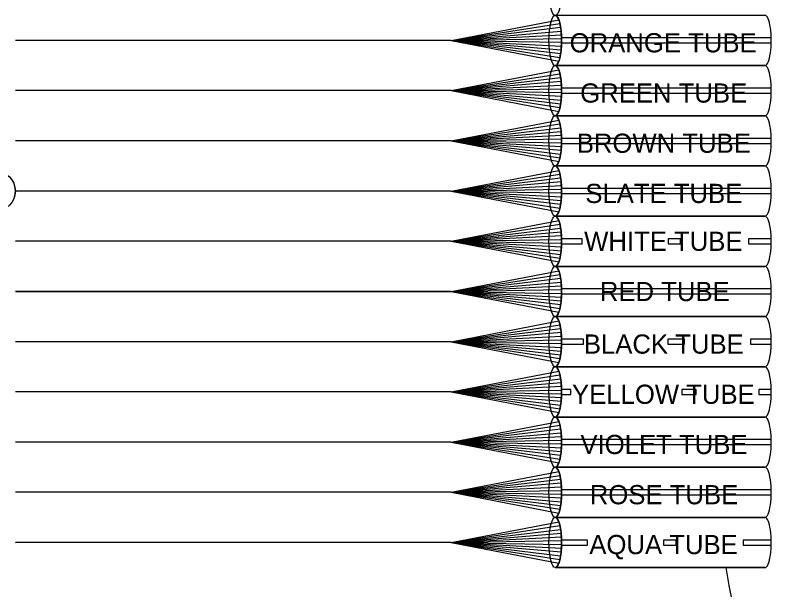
# Model space of a CAD drawing. Extents: x 1805893 to 1833564, y 708898 to 716199.
# Drawn here: x 1831739.1 to 1831830.8, y 715850.1 to 715918.7 of the extents above; entities that cross this region are included whole.
import ezdxf

# ---------------------------------------------------------------- set-up
doc = ezdxf.new("R2010")
doc.units = 0
doc.layers.add('SH_Data', color=7, linetype='Continuous')

msp = doc.modelspace()

# ---------------------------------------------------------------- linework, layer by layer
at = {"layer": 'SH_Data'}
for p, q in [((1831828.682, 715918.733), (1831803.631, 715918.733)), ((1831791.211, 715915.733), (1831804.055, 715918.208)), ((1831791.211, 715915.733), (1831804.185, 715917.758)), ((1831791.211, 715915.733), (1831804.27, 715917.308)), ((1831791.211, 715915.733), (1831804.327, 715916.858)), ((1831791.211, 715915.733), (1831739.139, 715915.733)), ((1831791.211, 715915.733), (1831739.139, 715915.733)), ((1831791.211, 715915.733), (1831804.362, 715916.408)), ((1831791.211, 715915.733), (1831804.379, 715915.958)), ((1831791.211, 715915.733), (1831804.327, 715914.608)), ((1831791.211, 715915.733), (1831804.27, 715914.158)), ((1831791.211, 715915.733), (1831804.185, 715913.708)), ((1831791.211, 715915.733), (1831804.055, 715913.258)), ((1831791.211, 715915.733), (1831804.362, 715915.058)), ((1831791.211, 715915.733), (1831804.379, 715915.508)), ((1831791.211, 715909.733), (1831804.055, 715912.208)), ((1831828.682, 715912.733), (1831803.631, 715912.733)), ((1831803.631, 715912.733), (1831828.682, 715912.733)), ((1831791.211, 715909.733), (1831804.185, 715911.758)), ((1831791.211, 715909.733), (1831804.27, 715911.308)), ((1831791.211, 715909.733), (1831804.327, 715910.858)), ((1831791.211, 715909.733), (1831804.362, 715910.408)), ((1831791.211, 715909.733), (1831739.139, 715909.733)), ((1831791.211, 715909.733), (1831739.139, 715909.733)), ((1831791.211, 715909.733), (1831804.379, 715909.958)), ((1831791.211, 715909.733), (1831804.327, 715908.608)), ((1831791.211, 715909.733), (1831804.27, 715908.158)), ((1831791.211, 715909.733), (1831804.185, 715907.708)), ((1831791.211, 715909.733), (1831804.055, 715907.258)), ((1831791.211, 715909.733), (1831804.362, 715909.058)), ((1831791.211, 715909.733), (1831804.379, 715909.508)), ((1831803.631, 715906.733), (1831828.682, 715906.733)), ((1831828.682, 715906.733), (1831803.631, 715906.733)), ((1831791.211, 715903.733), (1831804.055, 715906.208)), ((1831791.211, 715903.733), (1831804.185, 715905.758)), ((1831791.211, 715903.733), (1831804.27, 715905.308)), ((1831791.211, 715903.733), (1831804.327, 715904.858)), ((1831791.211, 715903.733), (1831739.139, 715903.733)), ((1831791.211, 715903.733), (1831739.139, 715903.733)), ((1831791.211, 715903.733), (1831804.362, 715904.408)), ((1831791.211, 715903.733), (1831804.379, 715903.958)), ((1831791.211, 715903.733), (1831804.327, 715902.608)), ((1831791.211, 715903.733), (1831804.27, 715902.158)), ((1831791.211, 715903.733), (1831804.185, 715901.708)), ((1831791.211, 715903.733), (1831804.055, 715901.258)), ((1831791.211, 715903.733), (1831804.362, 715903.058)), ((1831791.211, 715903.733), (1831804.379, 715903.508)), ((1831791.211, 715897.733), (1831804.055, 715900.208)), ((1831803.631, 715900.733), (1831828.682, 715900.733)), ((1831828.682, 715900.733), (1831803.631, 715900.733)), ((1831791.211, 715897.733), (1831804.185, 715899.758)), ((1831791.211, 715897.733), (1831804.27, 715899.308)), ((1831791.211, 715897.733), (1831804.327, 715898.858)), ((1831791.211, 715897.733), (1831804.362, 715898.408)), ((1831791.211, 715897.733), (1831739.139, 715897.733)), ((1831791.211, 715897.733), (1831739.139, 715897.733)), ((1831791.211, 715897.733), (1831804.379, 715897.958)), ((1831791.211, 715897.733), (1831804.327, 715896.608)), ((1831791.211, 715897.733), (1831804.27, 715896.158)), ((1831791.211, 715897.733), (1831804.185, 715895.708)), ((1831791.211, 715897.733), (1831804.055, 715895.258)), ((1831791.211, 715897.733), (1831804.362, 715897.058)), ((1831791.211, 715897.733), (1831804.379, 715897.508)), ((1831803.631, 715894.733), (1831828.682, 715894.733)), ((1831828.682, 715894.733), (1831803.631, 715894.733)), ((1831791.211, 715891.733), (1831804.055, 715894.208)), ((1831791.211, 715891.733), (1831804.185, 715893.758)), ((1831791.211, 715891.733), (1831804.27, 715893.308)), ((1831791.211, 715891.733), (1831804.327, 715892.858)), ((1831791.211, 715891.733), (1831739.139, 715891.711)), ((1831791.211, 715891.733), (1831739.139, 715891.733)), ((1831791.211, 715891.733), (1831804.362, 715892.408)), ((1831791.211, 715891.733), (1831804.379, 715891.958)), ((1831791.211, 715891.733), (1831804.327, 715890.608)), ((1831791.211, 715891.733), (1831804.27, 715890.158)), ((1831791.211, 715891.733), (1831804.185, 715889.708)), ((1831791.211, 715891.733), (1831804.055, 715889.258)), ((1831791.211, 715891.733), (1831804.362, 715891.058)), ((1831791.211, 715891.733), (1831804.379, 715891.508)), ((1831791.211, 715885.733), (1831804.055, 715888.208)), ((1831803.631, 715888.733), (1831828.682, 715888.733)), ((1831828.682, 715888.733), (1831803.631, 715888.733)), ((1831791.211, 715885.733), (1831804.185, 715887.758)), ((1831791.211, 715885.733), (1831804.27, 715887.308)), ((1831791.211, 715885.733), (1831804.327, 715886.858)), ((1831791.211, 715885.733), (1831804.362, 715886.408)), ((1831739.139, 715885.733), (1831791.211, 715885.733)), ((1831791.211, 715885.733), (1831739.139, 715885.733)), ((1831791.211, 715885.733), (1831804.379, 715885.958)), ((1831791.211, 715885.733), (1831804.327, 715884.608)), ((1831791.211, 715885.733), (1831804.27, 715884.158)), ((1831791.211, 715885.733), (1831804.185, 715883.708)), ((1831791.211, 715885.733), (1831804.055, 715883.258)), ((1831791.211, 715885.733), (1831804.362, 715885.058)), ((1831791.211, 715885.733), (1831804.379, 715885.508)), ((1831803.631, 715882.733), (1831828.682, 715882.733)), ((1831828.682, 715882.733), (1831803.631, 715882.733)), ((1831791.211, 715879.733), (1831804.055, 715882.208)), ((1831791.211, 715879.733), (1831804.185, 715881.758)), ((1831791.211, 715879.733), (1831804.27, 715881.308)), ((1831791.211, 715879.733), (1831804.327, 715880.858)), ((1831791.211, 715879.733), (1831804.362, 715880.408)), ((1831791.211, 715879.733), (1831804.379, 715879.958)), ((1831791.211, 715879.733), (1831739.139, 715879.733)), ((1831791.211, 715879.733), (1831739.139, 715879.733)), ((1831791.211, 715879.733), (1831804.327, 715878.608)), ((1831791.211, 715879.733), (1831804.27, 715878.158)), ((1831791.211, 715879.733), (1831804.185, 715877.708)), ((1831791.211, 715879.733), (1831804.055, 715877.258)), ((1831791.211, 715879.733), (1831804.362, 715879.058)), ((1831791.211, 715879.733), (1831804.379, 715879.508)), ((1831791.211, 715873.733), (1831804.055, 715876.208)), ((1831828.682, 715876.733), (1831803.631, 715876.733)), ((1831803.631, 715876.733), (1831828.682, 715876.733)), ((1831791.211, 715873.733), (1831804.185, 715875.758)), ((1831791.211, 715873.733), (1831804.27, 715875.308)), ((1831791.211, 715873.733), (1831804.327, 715874.858)), ((1831791.211, 715873.733), (1831804.362, 715874.408)), ((1831791.211, 715873.733), (1831739.139, 715873.733)), ((1831791.211, 715873.733), (1831739.139, 715873.733)), ((1831791.211, 715873.733), (1831804.379, 715873.958)), ((1831791.211, 715873.733), (1831804.327, 715872.608)), ((1831791.211, 715873.733), (1831804.27, 715872.158)), ((1831791.211, 715873.733), (1831804.185, 715871.708)), ((1831791.211, 715873.733), (1831804.055, 715871.258)), ((1831791.211, 715873.733), (1831804.362, 715873.058)), ((1831791.211, 715873.733), (1831804.379, 715873.508)), ((1831803.631, 715870.733), (1831828.682, 715870.733)), ((1831828.682, 715870.733), (1831803.631, 715870.733)), ((1831791.211, 715867.733), (1831804.055, 715870.208)), ((1831791.211, 715867.733), (1831804.185, 715869.758)), ((1831791.211, 715867.733), (1831804.27, 715869.308)), ((1831791.211, 715867.733), (1831804.327, 715868.858)), ((1831791.211, 715867.733), (1831804.362, 715868.408)), ((1831791.211, 715867.733), (1831804.379, 715867.958)), ((1831791.211, 715867.733), (1831739.139, 715867.733)), ((1831791.211, 715867.733), (1831739.139, 715867.733)), ((1831791.211, 715867.733), (1831804.327, 715866.608)), ((1831791.211, 715867.733), (1831804.27, 715866.158)), ((1831791.211, 715867.733), (1831804.185, 715865.708)), ((1831791.211, 715867.733), (1831804.055, 715865.258)), ((1831791.211, 715867.733), (1831804.362, 715867.058)), ((1831791.211, 715867.733), (1831804.379, 715867.508)), ((1831791.211, 715861.733), (1831804.055, 715864.208)), ((1831803.631, 715864.733), (1831828.682, 715864.733)), ((1831828.682, 715864.733), (1831803.631, 715864.733)), ((1831791.211, 715861.733), (1831804.185, 715863.758)), ((1831791.211, 715861.733), (1831804.27, 715863.308)), ((1831791.211, 715861.733), (1831804.327, 715862.858)), ((1831791.211, 715861.733), (1831804.362, 715862.408)), ((1831791.211, 715861.733), (1831739.139, 715861.733)), ((1831791.211, 715861.733), (1831739.139, 715861.733)), ((1831791.211, 715861.733), (1831804.379, 715861.958)), ((1831791.211, 715861.733), (1831804.327, 715860.608)), ((1831791.211, 715861.733), (1831804.27, 715860.158)), ((1831791.211, 715861.733), (1831804.185, 715859.708)), ((1831791.211, 715861.733), (1831804.055, 715859.258)), ((1831791.211, 715861.733), (1831804.362, 715861.058)), ((1831791.211, 715861.733), (1831804.379, 715861.508)), ((1831803.631, 715858.733), (1831828.682, 715858.733)), ((1831828.682, 715858.733), (1831803.631, 715858.733)), ((1831791.211, 715855.733), (1831804.055, 715858.208)), ((1831791.211, 715855.733), (1831804.185, 715857.758)), ((1831791.211, 715855.733), (1831804.27, 715857.308)), ((1831791.211, 715855.733), (1831804.327, 715856.858)), ((1831791.211, 715855.733), (1831804.362, 715856.408)), ((1831791.211, 715855.733), (1831804.379, 715855.958)), ((1831791.211, 715855.733), (1831739.139, 715855.711)), ((1831791.211, 715855.733), (1831739.139, 715855.733)), ((1831791.211, 715855.733), (1831804.327, 715854.608)), ((1831791.211, 715855.733), (1831804.27, 715854.158)), ((1831791.211, 715855.733), (1831804.185, 715853.708)), ((1831791.211, 715855.733), (1831804.055, 715853.258)), ((1831791.211, 715855.733), (1831804.362, 715855.058)), ((1831791.211, 715855.733), (1831804.379, 715855.508)), ((1831803.631, 715852.733), (1831828.682, 715852.733)), ((1831828.682, 715852.733), (1831803.631, 715852.733)), ((1831803.631, 715852.733), (1831823.99, 715852.733))]:
    msp.add_line(p, q, dxfattribs=at)
for points in [[(1831829.428, 715916.033), (1831804.38, 715916.033), (1831804.38, 715915.433), (1831829.428, 715915.433)], [(1831829.428, 715910.033), (1831804.38, 715910.033), (1831804.38, 715909.433), (1831829.428, 715909.433)], [(1831829.428, 715904.033), (1831804.38, 715904.033), (1831804.38, 715903.433), (1831829.428, 715903.433)], [(1831829.428, 715898.033), (1831804.38, 715898.033), (1831804.38, 715897.433), (1831829.428, 715897.433)], [(1831806.864, 715892.033), (1831804.377, 715892.033), (1831804.377, 715891.433), (1831806.864, 715891.433)], [(1831818.596, 715892.033), (1831817.112, 715892.033), (1831817.112, 715891.433), (1831818.596, 715891.433)], [(1831829.428, 715892.033), (1831826.702, 715892.033), (1831826.702, 715891.433), (1831829.428, 715891.433)], [(1831829.428, 715886.033), (1831804.38, 715886.033), (1831804.38, 715885.433), (1831829.428, 715885.433)], [(1831806.986, 715880.033), (1831804.377, 715880.033), (1831804.377, 715879.433), (1831806.986, 715879.433)], [(1831819.051, 715880.033), (1831817.079, 715880.033), (1831817.079, 715879.433), (1831819.051, 715879.433)], [(1831829.428, 715880.033), (1831826.951, 715880.033), (1831826.951, 715879.433), (1831829.428, 715879.433)], [(1831805.505, 715874.033), (1831804.377, 715874.033), (1831804.377, 715873.433), (1831805.505, 715873.433)], [(1831820.464, 715874.033), (1831818.744, 715874.033), (1831818.744, 715873.433), (1831820.464, 715873.433)], [(1831829.428, 715874.033), (1831827.964, 715874.033), (1831827.964, 715873.433), (1831829.428, 715873.433)], [(1831829.428, 715868.033), (1831804.38, 715868.033), (1831804.38, 715867.433), (1831829.428, 715867.433)], [(1831829.428, 715862.033), (1831804.38, 715862.033), (1831804.38, 715861.433), (1831829.428, 715861.433)], [(1831807.481, 715856.033), (1831804.377, 715856.033), (1831804.377, 715855.433), (1831807.481, 715855.433)], [(1831818.064, 715856.033), (1831816.547, 715856.033), (1831816.547, 715855.433), (1831818.064, 715855.433)], [(1831829.428, 715856.033), (1831826.06, 715856.033), (1831826.06, 715855.433), (1831829.428, 715855.433)]]:
    msp.add_lwpolyline(points, close=True, dxfattribs=at)
msp.add_circle((1831736.727, 715897.733), 2.411, dxfattribs=at)
msp.add_arc((1831736.727, 715897.733), 2.411, 332.353, 27.647, dxfattribs=at)
for centre, major_axis, ratio, start_param, end_param in [((1831829.285, 715924.733), (0, -86.094), 0.112175, 5.702888, 10.005075), ((1831829.285, 715924.733), (0, -86.094), 0.112175, 5.702888, 10.005075), ((1831803.631, 715915.733), (0, -3), 0.25, 0, 3.141593), ((1831828.682, 715915.733), (0, -3), 0.25, 0, 3.141593), ((1831828.682, 715915.733), (0, -3), 0.25, 0, 3.141593), ((1831803.631, 715909.733), (0, -3), 0.25, 0, 3.141593), ((1831828.682, 715909.733), (0, -3), 0.25, 0, 3.141593), ((1831828.682, 715909.733), (0, -3), 0.25, 0, 3.141593), ((1831803.631, 715903.733), (0, -3), 0.25, 0, 3.141593), ((1831828.682, 715903.733), (0, -3), 0.25, 0, 3.141593), ((1831828.682, 715903.733), (0, -3), 0.25, 0, 3.141593), ((1831803.631, 715897.733), (0, -3), 0.25, 0, 3.141593), ((1831828.682, 715897.733), (0, -3), 0.25, 0, 3.141593), ((1831828.682, 715897.733), (0, -3), 0.25, 0, 3.141593), ((1831803.631, 715891.733), (0, -3), 0.25, 0, 3.141593), ((1831828.682, 715891.733), (0, -3), 0.25, 0, 3.141593), ((1831828.682, 715891.733), (0, -3), 0.25, 0, 3.141593), ((1831803.631, 715885.733), (0, -3), 0.25, 0, 3.141593), ((1831828.682, 715885.733), (0, -3), 0.25, 0, 3.141593), ((1831828.682, 715885.733), (0, -3), 0.25, 0, 3.141593), ((1831803.631, 715879.733), (0, -3), 0.25, 0, 3.141593), ((1831828.682, 715879.733), (0, -3), 0.25, 0, 3.141593), ((1831828.682, 715879.733), (0, -3), 0.25, 0, 3.141593), ((1831803.631, 715873.733), (0, -3), 0.25, 0, 3.141593), ((1831828.682, 715873.733), (0, -3), 0.25, 0, 3.141593), ((1831828.682, 715873.733), (0, -3), 0.25, 0, 3.141593), ((1831803.631, 715867.733), (0, -3), 0.25, 0, 3.141593), ((1831828.682, 715867.733), (0, -3), 0.25, 0, 3.141593), ((1831828.682, 715867.733), (0, -3), 0.25, 0, 3.141593), ((1831803.631, 715861.733), (0, -3), 0.25, 0, 3.141593), ((1831828.682, 715861.733), (0, -3), 0.25, 0, 3.141593), ((1831828.682, 715861.733), (0, -3), 0.25, 0, 3.141593), ((1831803.631, 715855.733), (0, -3), 0.25, 0, 3.141593), ((1831828.682, 715855.733), (0, -3), 0.25, 0, 3.141593), ((1831828.682, 715855.733), (0, -3), 0.25, 0, 3.141593)]:
    msp.add_ellipse(centre, major_axis=major_axis, ratio=ratio, start_param=start_param, end_param=end_param, dxfattribs=at)
for centre in [(1831803.631, 715921.733), (1831803.631, 715915.733), (1831803.631, 715909.733), (1831803.631, 715903.733), (1831803.631, 715897.733), (1831803.631, 715891.733), (1831803.631, 715885.733), (1831803.631, 715879.733), (1831803.631, 715873.733), (1831803.631, 715867.733), (1831803.631, 715861.733), (1831803.631, 715855.733)]:
    msp.add_ellipse(centre, major_axis=(0, -3), ratio=0.25, dxfattribs=at)

# ---------------------------------------------------------------- texts
for s, height, p in [('ORANGE TUBE', 2.29468, (1831805.356, 715914.304)), ('GREEN TUBE', 2.2947, (1831806.611, 715908.304)), ('BROWN TUBE', 2.2947, (1831806.199, 715902.304)), ('SLATE TUBE', 2.2947, (1831807.22, 715896.304)), ('WHITE TUBE', 2.2947, (1831807.081, 715890.585)), ('RED TUBE', 2.2947, (1831808.959, 715884.585)), ('BLACK TUBE', 2.2947, (1831807.047, 715878.304)), ('YELLOW TUBE', 2.29468, (1831805.632, 715872.304)), ('VIOLET TUBE', 2.29468, (1831806.642, 715866.304)), ('ROSE TUBE', 2.2947, (1831807.755, 715860.304)), ('AQUA TUBE', 2.2947, (1831807.702, 715854.344))]:
    msp.add_text(s, height=height, dxfattribs=at).set_placement(p)

doc.saveas('drawing.dxf')
